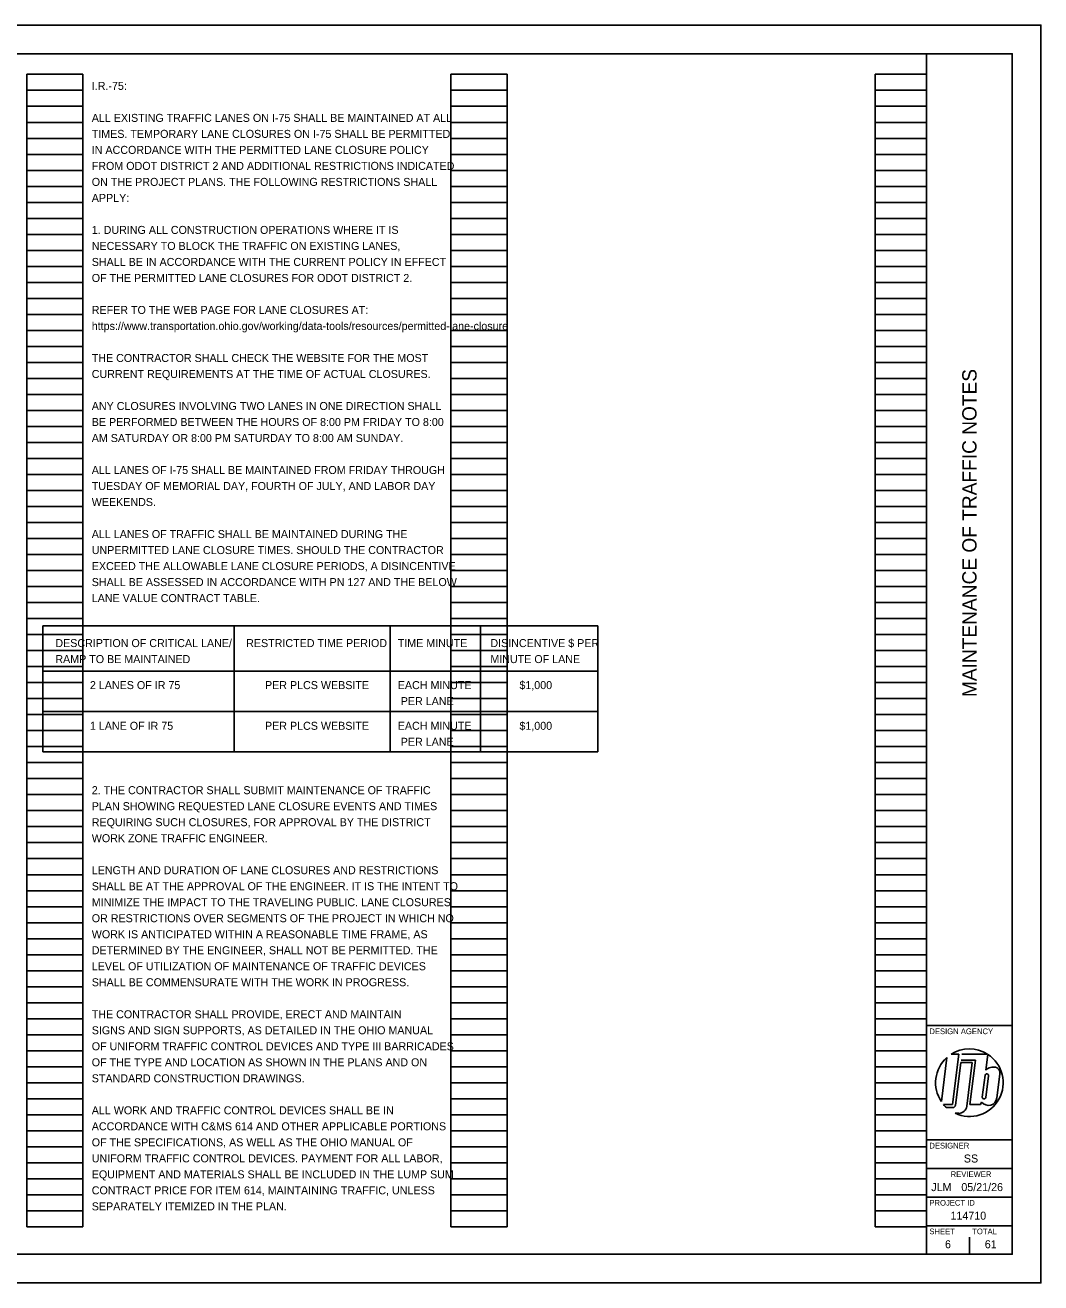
# Model space of a CAD drawing. Extents: x 0 to 257, y -39 to 22.
# Drawn here: x 16.23 to 34, y 0 to 22 of the extents above; entities that cross this region are included whole.
import ezdxf

# ---------------------------------------------------------------- set-up
doc = ezdxf.new("R2010")
doc.units = 0
for name, color, linetype in [('SH_Border', 7, 'Continuous'), ('SH_Cut_Line', 7, 'Continuous'), ('SH_Data', 7, 'Continuous'), ('SH_Text', 7, 'Continuous')]:
    doc.layers.add(name, color=color, linetype=linetype)

msp = doc.modelspace()

# ---------------------------------------------------------------- linework, layer by layer
at = {"layer": 'SH_Border'}
msp.add_lwpolyline([(0, 0), (34, 0), (34, 22), (0, 22)], close=True, dxfattribs=at)
at = {"layer": 'SH_Cut_Line'}
for p, q in [((32, 0.5), (32, 21.5)), ((32, 4.5), (33.5, 4.5)), ((32, 2.5), (33.5, 2.5)), ((32, 2), (33.5, 2)), ((32, 1.5), (33.5, 1.5)), ((32, 1), (33.5, 1))]:
    msp.add_line(p, q, dxfattribs=at)
msp.add_lwpolyline([(1.5, 21.5), (33.5, 21.5), (33.5, 0.5), (1.5, 0.5)], close=True, dxfattribs=at)
at = {"layer": 'SH_Data'}
for p, q in [((16.26, 0.98), (16.26, 21.14)), ((16.26, 21.14), (17.24, 21.14)), ((17.24, 0.98), (17.24, 21.14)), ((23.68, 0.98), (23.68, 21.14)), ((23.68, 21.14), (24.66, 21.14)), ((24.66, 0.98), (24.66, 21.14)), ((31.1, 0.98), (31.1, 21.14)), ((31.1, 21.14), (32, 21.14)), ((32, 0.98), (32, 21.14)), ((16.26, 20.86), (17.24, 20.86)), ((23.68, 20.86), (24.66, 20.86)), ((31.1, 20.86), (32, 20.86)), ((16.26, 20.58), (17.24, 20.58)), ((23.68, 20.58), (24.66, 20.58)), ((31.1, 20.58), (32, 20.58)), ((16.26, 20.3), (17.24, 20.3)), ((23.68, 20.3), (24.66, 20.3)), ((31.1, 20.3), (32, 20.3)), ((16.26, 20.02), (17.24, 20.02)), ((23.68, 20.02), (24.66, 20.02)), ((31.1, 20.02), (32, 20.02)), ((16.26, 19.74), (17.24, 19.74)), ((23.68, 19.74), (24.66, 19.74)), ((31.1, 19.74), (32, 19.74)), ((16.26, 19.46), (17.24, 19.46)), ((23.68, 19.46), (24.66, 19.46)), ((31.1, 19.46), (32, 19.46)), ((16.26, 19.18), (17.24, 19.18)), ((23.68, 19.18), (24.66, 19.18)), ((31.1, 19.18), (32, 19.18)), ((16.26, 18.9), (17.24, 18.9)), ((23.68, 18.9), (24.66, 18.9)), ((31.1, 18.9), (32, 18.9)), ((16.26, 18.62), (17.24, 18.62)), ((23.68, 18.62), (24.66, 18.62)), ((31.1, 18.62), (32, 18.62)), ((16.26, 18.34), (17.24, 18.34)), ((23.68, 18.34), (24.66, 18.34)), ((31.1, 18.34), (32, 18.34)), ((16.26, 18.06), (17.24, 18.06)), ((23.68, 18.06), (24.66, 18.06)), ((31.1, 18.06), (32, 18.06)), ((16.26, 17.78), (17.24, 17.78)), ((23.68, 17.78), (24.66, 17.78)), ((31.1, 17.78), (32, 17.78)), ((16.26, 17.5), (17.24, 17.5)), ((23.68, 17.5), (24.66, 17.5)), ((31.1, 17.5), (32, 17.5)), ((16.26, 17.22), (17.24, 17.22)), ((23.68, 17.22), (24.66, 17.22)), ((31.1, 17.22), (32, 17.22)), ((16.26, 16.94), (17.24, 16.94)), ((23.68, 16.94), (24.66, 16.94)), ((31.1, 16.94), (32, 16.94)), ((16.26, 16.66), (17.24, 16.66)), ((23.68, 16.66), (24.66, 16.66)), ((31.1, 16.66), (32, 16.66)), ((16.26, 16.38), (17.24, 16.38)), ((23.68, 16.38), (24.66, 16.38)), ((31.1, 16.38), (32, 16.38)), ((16.26, 16.1), (17.24, 16.1)), ((23.68, 16.1), (24.66, 16.1)), ((31.1, 16.1), (32, 16.1)), ((16.26, 15.82), (17.24, 15.82)), ((23.68, 15.82), (24.66, 15.82)), ((31.1, 15.82), (32, 15.82)), ((16.26, 15.54), (17.24, 15.54)), ((23.68, 15.54), (24.66, 15.54)), ((31.1, 15.54), (32, 15.54)), ((16.26, 15.26), (17.24, 15.26)), ((23.68, 15.26), (24.66, 15.26)), ((31.1, 15.26), (32, 15.26)), ((16.26, 14.98), (17.24, 14.98)), ((23.68, 14.98), (24.66, 14.98)), ((31.1, 14.98), (32, 14.98)), ((16.26, 14.7), (17.24, 14.7)), ((23.68, 14.7), (24.66, 14.7)), ((31.1, 14.7), (32, 14.7)), ((16.26, 14.42), (17.24, 14.42)), ((23.68, 14.42), (24.66, 14.42)), ((31.1, 14.42), (32, 14.42)), ((16.26, 14.14), (17.24, 14.14)), ((23.68, 14.14), (24.66, 14.14)), ((31.1, 14.14), (32, 14.14)), ((16.26, 13.86), (17.24, 13.86)), ((23.68, 13.86), (24.66, 13.86)), ((31.1, 13.86), (32, 13.86)), ((16.26, 13.58), (17.24, 13.58)), ((23.68, 13.58), (24.66, 13.58)), ((31.1, 13.58), (32, 13.58)), ((16.26, 13.3), (17.24, 13.3)), ((23.68, 13.3), (24.66, 13.3)), ((31.1, 13.3), (32, 13.3)), ((16.26, 13.02), (17.24, 13.02)), ((23.68, 13.02), (24.66, 13.02)), ((31.1, 13.02), (32, 13.02)), ((16.26, 12.74), (17.24, 12.74)), ((23.68, 12.74), (24.66, 12.74)), ((31.1, 12.74), (32, 12.74)), ((16.26, 12.46), (17.24, 12.46)), ((23.68, 12.46), (24.66, 12.46)), ((31.1, 12.46), (32, 12.46)), ((16.26, 12.18), (17.24, 12.18)), ((23.68, 12.18), (24.66, 12.18)), ((31.1, 12.18), (32, 12.18)), ((16.26, 11.9), (17.24, 11.9)), ((23.68, 11.9), (24.66, 11.9)), ((31.1, 11.9), (32, 11.9)), ((16.26, 11.62), (17.24, 11.62)), ((23.68, 11.62), (24.66, 11.62)), ((31.1, 11.62), (32, 11.62)), ((16.26, 11.34), (17.24, 11.34)), ((23.68, 11.34), (24.66, 11.34)), ((31.1, 11.34), (32, 11.34)), ((16.26, 11.06), (17.24, 11.06)), ((23.68, 11.06), (24.66, 11.06)), ((31.1, 11.06), (32, 11.06)), ((16.26, 10.78), (17.24, 10.78)), ((23.68, 10.78), (24.66, 10.78)), ((31.1, 10.78), (32, 10.78)), ((16.26, 10.5), (17.24, 10.5)), ((23.68, 10.5), (24.66, 10.5)), ((31.1, 10.5), (32, 10.5)), ((16.26, 10.22), (17.24, 10.22)), ((23.68, 10.22), (24.66, 10.22)), ((31.1, 10.22), (32, 10.22)), ((16.26, 9.94), (17.24, 9.94)), ((23.68, 9.94), (24.66, 9.94)), ((31.1, 9.94), (32, 9.94)), ((16.26, 9.66), (17.24, 9.66)), ((23.68, 9.66), (24.66, 9.66)), ((31.1, 9.66), (32, 9.66)), ((16.26, 9.38), (17.24, 9.38)), ((23.68, 9.38), (24.66, 9.38)), ((31.1, 9.38), (32, 9.38)), ((16.26, 9.1), (17.24, 9.1)), ((23.68, 9.1), (24.66, 9.1)), ((31.1, 9.1), (32, 9.1)), ((16.26, 8.82), (17.24, 8.82)), ((23.68, 8.82), (24.66, 8.82)), ((31.1, 8.82), (32, 8.82)), ((16.26, 8.54), (17.24, 8.54)), ((23.68, 8.54), (24.66, 8.54)), ((31.1, 8.54), (32, 8.54)), ((16.26, 8.26), (17.24, 8.26)), ((23.68, 8.26), (24.66, 8.26)), ((31.1, 8.26), (32, 8.26)), ((16.26, 7.98), (17.24, 7.98)), ((23.68, 7.98), (24.66, 7.98)), ((31.1, 7.98), (32, 7.98)), ((16.26, 7.7), (17.24, 7.7)), ((23.68, 7.7), (24.66, 7.7)), ((31.1, 7.7), (32, 7.7)), ((16.26, 7.42), (17.24, 7.42)), ((23.68, 7.42), (24.66, 7.42)), ((31.1, 7.42), (32, 7.42)), ((16.26, 7.14), (17.24, 7.14)), ((23.68, 7.14), (24.66, 7.14)), ((31.1, 7.14), (32, 7.14)), ((16.26, 6.86), (17.24, 6.86)), ((23.68, 6.86), (24.66, 6.86)), ((31.1, 6.86), (32, 6.86)), ((16.26, 6.58), (17.24, 6.58)), ((23.68, 6.58), (24.66, 6.58)), ((31.1, 6.58), (32, 6.58)), ((16.26, 6.3), (17.24, 6.3)), ((23.68, 6.3), (24.66, 6.3)), ((31.1, 6.3), (32, 6.3)), ((16.26, 6.02), (17.24, 6.02)), ((23.68, 6.02), (24.66, 6.02)), ((31.1, 6.02), (32, 6.02)), ((16.26, 5.74), (17.24, 5.74)), ((23.68, 5.74), (24.66, 5.74)), ((31.1, 5.74), (32, 5.74)), ((16.26, 5.46), (17.24, 5.46)), ((23.68, 5.46), (24.66, 5.46)), ((31.1, 5.46), (32, 5.46)), ((16.26, 5.18), (17.24, 5.18)), ((23.68, 5.18), (24.66, 5.18)), ((31.1, 5.18), (32, 5.18)), ((16.26, 4.9), (17.24, 4.9)), ((23.68, 4.9), (24.66, 4.9)), ((31.1, 4.9), (32, 4.9)), ((16.26, 4.62), (17.24, 4.62)), ((23.68, 4.62), (24.66, 4.62)), ((31.1, 4.62), (32, 4.62)), ((16.26, 4.34), (17.24, 4.34)), ((23.68, 4.34), (24.66, 4.34)), ((31.1, 4.34), (32, 4.34)), ((16.26, 4.06), (17.24, 4.06)), ((23.68, 4.06), (24.66, 4.06)), ((31.1, 4.06), (32, 4.06)), ((32.432, 3.998), (32.567, 3.998)), ((32.567, 3.998), (32.456, 3.118)), ((32.617, 4), (33.065, 4)), ((33.07, 3.996), (33.035, 3.72)), ((16.26, 3.78), (17.24, 3.78)), ((23.68, 3.78), (24.66, 3.78)), ((31.1, 3.78), (32, 3.78)), ((32.356, 3.94), (32.259, 3.171)), ((32.504, 3.104), (32.599, 3.855)), ((32.599, 3.855), (32.801, 3.855)), ((32.856, 3.896), (32.604, 3.896)), ((32.801, 3.855), (32.704, 3.089)), ((32.758, 3.118), (32.856, 3.896)), ((33.024, 3.631), (32.976, 3.25)), ((33.036, 3.243), (33.084, 3.624)), ((33.283, 3.648), (33.231, 3.237)), ((16.26, 3.5), (17.24, 3.5)), ((23.68, 3.5), (24.66, 3.5)), ((31.1, 3.5), (32, 3.5)), ((32.75, 3.5), (32.75, 3.5)), ((16.26, 3.22), (17.24, 3.22)), ((23.68, 3.22), (24.66, 3.22)), ((31.1, 3.22), (32, 3.22)), ((32.456, 3.118), (32.299, 3.118)), ((32.947, 3.118), (32.758, 3.118)), ((32.964, 3.161), (32.947, 3.118)), ((16.26, 2.94), (17.24, 2.94)), ((23.68, 2.94), (24.66, 2.94)), ((31.1, 2.94), (32, 2.94)), ((32.347, 3.068), (32.462, 3.068)), ((32.564, 2.966), (32.498, 2.966)), ((16.26, 2.66), (17.24, 2.66)), ((23.68, 2.66), (24.66, 2.66)), ((31.1, 2.66), (32, 2.66)), ((16.26, 2.38), (17.24, 2.38)), ((23.68, 2.38), (24.66, 2.38)), ((31.1, 2.38), (32, 2.38)), ((16.26, 2.1), (17.24, 2.1)), ((23.68, 2.1), (24.66, 2.1)), ((31.1, 2.1), (32, 2.1)), ((16.26, 1.82), (17.24, 1.82)), ((23.68, 1.82), (24.66, 1.82)), ((31.1, 1.82), (32, 1.82)), ((16.26, 1.54), (17.24, 1.54)), ((23.68, 1.54), (24.66, 1.54)), ((31.1, 1.54), (32, 1.54)), ((16.26, 1.26), (17.24, 1.26)), ((23.68, 1.26), (24.66, 1.26)), ((31.1, 1.26), (32, 1.26)), ((16.26, 0.98), (17.24, 0.98)), ((23.68, 0.98), (24.66, 0.98)), ((31.1, 0.98), (32, 0.98)), ((32.375, 0.675), (32.375, 0.675)), ((32.75, 0.5), (32.75, 0.8))]:
    msp.add_line(p, q, dxfattribs=at)
for centre, radius, start, end in [((32.75, 3.5), 0.591, 57.726, 122.5688), ((32.75, 3.5), 0.591, 244.7646, 57.1575), ((32.75, 3.5), 0.591, 131.8253, 213.7822), ((33.17, 3.586), 0.19, 105.9444, 135.0487), ((33.164, 3.6), 0.175, 66.6782, 105.4185), ((33.177, 3.669), 0.108, 349.2072, 58.7163), ((33.054, 3.628), 0.0301, 352.3298, 173.2777), ((32.75, 3.5), 0.591, 220.2786, 227.0158), ((32.462, 3.109), 0.0417, 270, 352.8038), ((32.564, 3.106), 0.141, 270, 352.8038), ((33.081, 3.255), 0.151, 218.6264, 353.0883), ((33.006, 3.246), 0.0301, 172.3335, 353.274)]:
    msp.add_arc(centre, radius, start, end, dxfattribs=at)
at = {"layer": 'SH_Text'}
for p, q in [((16.541, 11.494), (26.248, 11.494)), ((16.541, 11.494), (16.541, 9.286)), ((19.888, 11.494), (19.888, 9.286)), ((22.616, 11.494), (22.616, 9.286)), ((24.197, 11.494), (24.197, 9.286)), ((26.248, 11.494), (26.248, 9.286)), ((16.541, 10.701), (26.248, 10.701)), ((16.541, 9.994), (26.248, 9.994)), ((16.541, 9.286), (26.248, 9.286))]:
    msp.add_line(p, q, dxfattribs=at)

# ---------------------------------------------------------------- texts
at = {"layer": 'SH_Data'}
msp.add_text('MAINTENANCE OF TRAFFIC NOTES', height=0.25, rotation=90, dxfattribs=at).set_placement((32.875, 10.247))
for s, height, p in [('DESIGN AGENCY', 0.1, (32.05, 4.35)), ('DESIGNER', 0.1, (32.05, 2.35)), ('SS', 0.14, (32.653, 2.105)), ('REVIEWER', 0.1, (32.422, 1.85)), ('JLM', 0.14, (32.083, 1.605)), ('05/21/26', 0.14, (32.609, 1.605)), ('PROJECT ID', 0.1, (32.05, 1.35)), ('114710', 0.14, (32.419, 1.105)), ('SHEET', 0.1, (32.05, 0.85)), ('TOTAL', 0.1, (32.8, 0.85)), ('6', 0.14, (32.323, 0.605)), ('61', 0.14, (33.019, 0.605))]:
    msp.add_text(s, height=height, dxfattribs=at).set_placement(p)
at = {"layer": 'SH_Text'}
for s, p in [('I.R.-75:', (17.395, 20.868)), ('ALL EXISTING TRAFFIC LANES ON I-75 SHALL BE MAINTAINED AT ALL', (17.395, 20.308)), ('TIMES. TEMPORARY LANE CLOSURES ON I-75 SHALL BE PERMITTED', (17.395, 20.028)), ('IN ACCORDANCE WITH THE PERMITTED LANE CLOSURE POLICY', (17.395, 19.748)), ('FROM ODOT DISTRICT 2 AND ADDITIONAL RESTRICTIONS INDICATED', (17.395, 19.468)), ('ON THE PROJECT PLANS. THE FOLLOWING RESTRICTIONS SHALL', (17.395, 19.188)), ('APPLY:', (17.395, 18.908)), ('1. DURING ALL CONSTRUCTION OPERATIONS WHERE IT IS', (17.395, 18.348)), ('NECESSARY TO BLOCK THE TRAFFIC ON EXISTING LANES,', (17.395, 18.068)), ('SHALL BE IN ACCORDANCE WITH THE CURRENT POLICY IN EFFECT', (17.395, 17.788)), ('OF THE PERMITTED LANE CLOSURES FOR ODOT DISTRICT 2.', (17.395, 17.508)), ('REFER TO THE WEB PAGE FOR LANE CLOSURES AT:', (17.395, 16.948)), ('https://www.transportation.ohio.gov/working/data-tools/resources/permitted-lane-closure', (17.395, 16.668)), ('THE CONTRACTOR SHALL CHECK THE WEBSITE FOR THE MOST', (17.395, 16.108)), ('CURRENT REQUIREMENTS AT THE TIME OF ACTUAL CLOSURES.', (17.395, 15.828)), ('ANY CLOSURES INVOLVING TWO LANES IN ONE DIRECTION SHALL', (17.395, 15.268)), ('BE PERFORMED BETWEEN THE HOURS OF 8:00 PM FRIDAY TO 8:00', (17.395, 14.988)), ('AM SATURDAY OR 8:00 PM SATURDAY TO 8:00 AM SUNDAY.', (17.395, 14.708)), ('ALL LANES OF I-75 SHALL BE MAINTAINED FROM FRIDAY THROUGH', (17.395, 14.148)), ('TUESDAY OF MEMORIAL DAY, FOURTH OF JULY, AND LABOR DAY ', (17.395, 13.868)), ('WEEKENDS.', (17.395, 13.588)), ('ALL LANES OF TRAFFIC SHALL BE MAINTAINED DURING THE', (17.395, 13.028)), ('UNPERMITTED LANE CLOSURE TIMES. SHOULD THE CONTRACTOR', (17.395, 12.748)), ('EXCEED THE ALLOWABLE LANE CLOSURE PERIODS, A DISINCENTIVE', (17.395, 12.468)), ('SHALL BE ASSESSED IN ACCORDANCE WITH PN 127 AND THE BELOW ', (17.395, 12.188)), ('LANE VALUE CONTRACT TABLE.', (17.395, 11.908)), ('DESCRIPTION OF CRITICAL LANE/ ', (16.758, 11.121)), ('RESTRICTED TIME PERIOD', (20.096, 11.121)), ('TIME MINUTE', (22.749, 11.121)), ('DISINCENTIVE $ PER ', (24.369, 11.121)), ('RAMP TO BE MAINTAINED', (16.758, 10.841)), ('MINUTE OF LANE', (24.369, 10.841)), ('2 LANES OF IR 75 ', (17.363, 10.386)), ('PER PLCS WEBSITE', (20.426, 10.386)), ('EACH MINUTE', (22.749, 10.386)), ('$1,000', (24.877, 10.386)), (' PER LANE', (22.749, 10.106)), ('1 LANE OF IR 75 ', (17.363, 9.674)), ('PER PLCS WEBSITE', (20.426, 9.674)), ('EACH MINUTE', (22.749, 9.674)), ('$1,000', (24.877, 9.674)), (' PER LANE', (22.749, 9.394)), ('2. THE CONTRACTOR SHALL SUBMIT MAINTENANCE OF TRAFFIC', (17.395, 8.548)), ('PLAN SHOWING REQUESTED LANE CLOSURE EVENTS AND TIMES', (17.395, 8.268)), ('REQUIRING SUCH CLOSURES, FOR APPROVAL BY THE DISTRICT', (17.395, 7.988)), ('WORK ZONE TRAFFIC ENGINEER.', (17.395, 7.708)), ('LENGTH AND DURATION OF LANE CLOSURES AND RESTRICTIONS', (17.395, 7.148)), ('SHALL BE AT THE APPROVAL OF THE ENGINEER. IT IS THE INTENT TO', (17.395, 6.868)), ('MINIMIZE THE IMPACT TO THE TRAVELING PUBLIC. LANE CLOSURES', (17.395, 6.588)), ('OR RESTRICTIONS OVER SEGMENTS OF THE PROJECT IN WHICH NO', (17.395, 6.308)), ('WORK IS ANTICIPATED WITHIN A REASONABLE TIME FRAME, AS', (17.395, 6.028)), ('DETERMINED BY THE ENGINEER, SHALL NOT BE PERMITTED. THE', (17.395, 5.748)), ('LEVEL OF UTILIZATION OF MAINTENANCE OF TRAFFIC DEVICES', (17.395, 5.468)), ('SHALL BE COMMENSURATE WITH THE WORK IN PROGRESS.', (17.395, 5.188)), ('THE CONTRACTOR SHALL PROVIDE, ERECT AND MAINTAIN ', (17.395, 4.628)), ('SIGNS AND SIGN SUPPORTS, AS DETAILED IN THE OHIO MANUAL', (17.395, 4.348)), ('OF UNIFORM TRAFFIC CONTROL DEVICES AND TYPE III BARRICADES', (17.395, 4.068)), ('OF THE TYPE AND LOCATION AS SHOWN IN THE PLANS AND ON ', (17.395, 3.788)), ('STANDARD CONSTRUCTION DRAWINGS.', (17.395, 3.508)), ('ALL WORK AND TRAFFIC CONTROL DEVICES SHALL BE IN', (17.395, 2.948)), ('ACCORDANCE WITH C&MS 614 AND OTHER APPLICABLE PORTIONS', (17.395, 2.668)), ('OF THE SPECIFICATIONS, AS WELL AS THE OHIO MANUAL OF', (17.395, 2.388)), ('UNIFORM TRAFFIC CONTROL DEVICES. PAYMENT FOR ALL LABOR,', (17.395, 2.108)), ('EQUIPMENT AND MATERIALS SHALL BE INCLUDED IN THE LUMP SUM', (17.395, 1.828)), ('CONTRACT PRICE FOR ITEM 614, MAINTAINING TRAFFIC, UNLESS', (17.395, 1.548)), ('SEPARATELY ITEMIZED IN THE PLAN.', (17.395, 1.268))]:
    msp.add_text(s, height=0.14, dxfattribs=at).set_placement(p)

doc.saveas('drawing.dxf')
